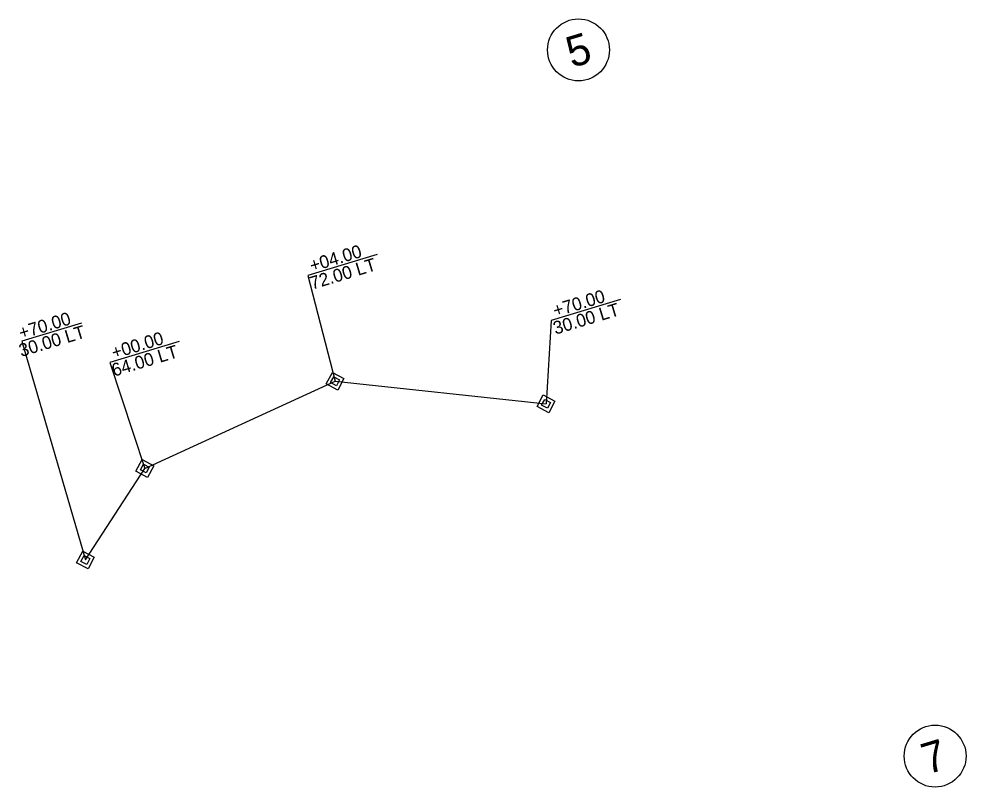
# Model space of a CAD drawing. Extents: x 1002576 to 1014655, y 551673 to 557994.
# Drawn here: x 1012064 to 1012431.3, y 552034.7 to 552332.5 of the extents above; entities that cross this region are included whole.
import ezdxf

# ---------------------------------------------------------------- set-up
doc = ezdxf.new("R2010")
doc.units = 0
for name, color, linetype in [('Exist Hydro Stream or Body of Water', 7, 'Continuous'), ('Exist Other Culture Area Outline', 7, 'Continuous'), ('Exist Roads EOP Other', 7, 'Continuous'), ('Exist Structure Major Deck Tunnel Box Culvert', 7, 'Continuous'), ('Exist Utilities Power Pole CELL', 7, 'Continuous')]:
    doc.layers.add(name, color=color, linetype=linetype)

msp = doc.modelspace()

# ---------------------------------------------------------------- linework, layer by layer
at = {"layer": 'Exist Hydro Stream or Body of Water'}
for p, q in [((1012186.59, 552192.04), (1012186.59, 552192.04)), ((1012268.41, 552183.28), (1012268.41, 552183.28)), ((1012112.82, 552158.18), (1012112.82, 552158.18)), ((1012089.76, 552122.73), (1012089.76, 552122.73))]:
    msp.add_line(p, q, dxfattribs=at)
at = {"layer": 'Exist Other Culture Area Outline'}
for p, q in [((1012112.82, 552158.18), (1012186.59, 552192.04)), ((1012186.59, 552192.04), (1012268.41, 552183.28)), ((1012089.76, 552122.73), (1012112.82, 552158.18))]:
    msp.add_line(p, q, dxfattribs=at)
at = {"layer": 'Exist Roads EOP Other'}
for p, q in [((1012202.96, 552241.18), (1012176.05, 552233.04)), ((1012297.32, 552223.75), (1012270.41, 552215.6)), ((1012088.2, 552214.5), (1012065.18, 552207.54)), ((1012126.11, 552207.46), (1012099.19, 552199.32))]:
    msp.add_line(p, q, dxfattribs=at)
for points in [[(1012176.05, 552233.04), (1012186.59, 552192.04)], [(1012270.41, 552215.6), (1012268.41, 552183.28)], [(1012065.18, 552207.54), (1012089.76, 552122.73)], [(1012099.19, 552199.32), (1012112.82, 552158.18)]]:
    msp.add_lwpolyline(points, dxfattribs=at)
at = {"layer": 'Exist Structure Major Deck Tunnel Box Culvert'}
for points in [[(1012190.03, 552193.08), (1012187.63, 552188.59), (1012183.14, 552190.99), (1012185.54, 552195.48)], [(1012188.31, 552192.56), (1012187.11, 552190.31), (1012184.86, 552191.52), (1012186.06, 552193.76)], [(1012271.85, 552184.33), (1012269.45, 552179.84), (1012264.96, 552182.24), (1012267.36, 552186.73)], [(1012270.13, 552183.8), (1012268.93, 552181.56), (1012266.68, 552182.76), (1012267.88, 552185.01)], [(1012116.26, 552159.22), (1012113.86, 552154.74), (1012109.37, 552157.14), (1012111.78, 552161.63)], [(1012114.54, 552158.7), (1012113.34, 552156.46), (1012111.1, 552157.66), (1012112.3, 552159.9)], [(1012093.21, 552123.77), (1012090.81, 552119.28), (1012086.32, 552121.68), (1012088.72, 552126.17)], [(1012091.49, 552123.25), (1012090.28, 552121), (1012088.04, 552122.2), (1012089.24, 552124.45)]]:
    msp.add_lwpolyline(points, close=True, dxfattribs=at)
at = {"layer": 'Exist Utilities Power Pole CELL'}
for p, q in [((1012280.99, 552320.5), (1012280.99, 552320.5)), ((1012419.3, 552046.68), (1012419.3, 552046.68))]:
    msp.add_line(p, q, dxfattribs=at)
for centre in [(1012280.99, 552320.5), (1012419.3, 552046.68)]:
    msp.add_circle(centre, 12, dxfattribs=at)

# ---------------------------------------------------------------- texts
at = {"layer": 'Exist Roads EOP Other'}
for s, p in [('+04.00', (1012177.63, 552234.33)), ('72.00 LT', (1012177.7, 552227.51)), ('+70.00', (1012271.99, 552216.9)), ('30.00 LT', (1012272.06, 552210.07)), ('+70.00', (1012064.81, 552208.24)), ('30.00 LT', (1012064.88, 552201.41)), ('+00.00', (1012100.78, 552200.61)), ('64.00 LT', (1012100.85, 552193.78))]:
    msp.add_text(s, height=5, rotation=16.8304, dxfattribs=at).set_placement(p)
at = {"layer": 'Exist Utilities Power Pole CELL'}
for s, p in [('5', (1012278.42, 552313.45)), ('7', (1012416.24, 552039.49))]:
    msp.add_text(s, height=12, rotation=16.8304, dxfattribs=at).set_placement(p)

doc.saveas('drawing.dxf')
